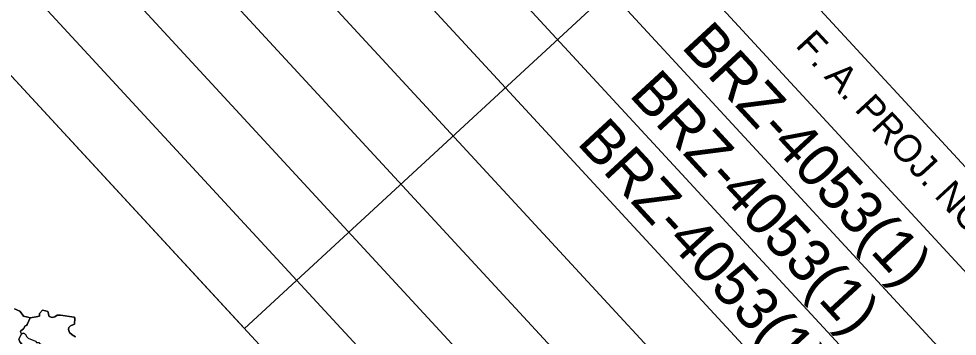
# Model space of a CAD drawing. Extents: x 1695041 to 1706254, y 786537 to 798223.
# Drawn here: x 1705302.9 to 1705798.2, y 794593.6 to 794761.2 of the extents above; entities that cross this region are included whole.
import ezdxf

# ---------------------------------------------------------------- set-up
doc = ezdxf.new("R2010")
doc.units = 0
for name, color, linetype in [('Old_Level_12', 7, 'Continuous'), ('Old_Level_20', 7, 'Continuous'), ('Sheet Data Field CELL', 7, 'Continuous'), ('Sheet Title CELL', 7, 'Continuous')]:
    doc.layers.add(name, color=color, linetype=linetype)

msp = doc.modelspace()

# ---------------------------------------------------------------- linework, layer by layer
at = {"layer": 'Old_Level_12'}
msp.add_lwpolyline([(1705795.09, 794193.47), (1705235.51, 794799.69), (1705053.77, 794631.93), (1705613.35, 794025.71)], close=True, dxfattribs=at)
at = {"layer": 'Old_Level_20'}
for points in [[(1705307.6, 794603.6), (1705305.47, 794604.25), (1705304.6, 794605.23), (1705303.49, 794606.78), (1705300.61, 794608.12)], [(1705300.61, 794608.12), (1705303.49, 794606.78), (1705304.6, 794605.23), (1705305.47, 794604.25), (1705307.6, 794603.6), (1705308.91, 794603.3)], [(1705308.91, 794603.3), (1705307.35, 794599.77), (1705306.94, 794599.3), (1705306.24, 794599), (1705305.34, 794597.53), (1705303.91, 794596.43), (1705303.86, 794595.84), (1705304.34, 794594.77), (1705302.96, 794592.03), (1705303.49, 794590.63), (1705304.49, 794589.47), (1705303.58, 794586.32), (1705302.57, 794585.14)], [(1705307.1, 794593.34), (1705306.56, 794594.37), (1705306.04, 794594.84), (1705305.33, 794595.19), (1705304.34, 794594.77), (1705303.86, 794595.84), (1705303.91, 794596.43), (1705305.34, 794597.53), (1705306.24, 794599), (1705306.94, 794599.3), (1705307.35, 794599.77), (1705308.91, 794603.3), (1705312.12, 794603.87), (1705313.75, 794604.17), (1705313.92, 794605.5), (1705315.35, 794607.26), (1705316.99, 794606.91), (1705318.16, 794606.7), (1705318.9, 794603.95), (1705320.47, 794603.55), (1705321.94, 794603.83), (1705323.18, 794604.69), (1705324.97, 794604.64)], [(1705332.89, 794593.24), (1705331.06, 794594.4), (1705329.74, 794595.62), (1705329.11, 794597.05), (1705329.24, 794598.17), (1705330.21, 794599.03), (1705332.29, 794600.02), (1705332.53, 794603.09), (1705332.09, 794603.72), (1705324.97, 794604.64), (1705323.18, 794604.69), (1705321.94, 794603.83), (1705320.47, 794603.55), (1705318.9, 794603.95), (1705318.16, 794606.7), (1705316.99, 794606.91), (1705315.35, 794607.26), (1705313.92, 794605.5), (1705313.75, 794604.17), (1705312.12, 794603.87), (1705308.91, 794603.3), (1705307.6, 794603.6)], [(1705324.97, 794604.64), (1705332.09, 794603.72), (1705332.53, 794603.09), (1705332.29, 794600.02), (1705330.21, 794599.03), (1705329.24, 794598.17), (1705329.11, 794597.05), (1705329.74, 794595.62), (1705331.06, 794594.4), (1705332.89, 794593.24)], [(1705302.57, 794585.14), (1705303.58, 794586.32), (1705304.49, 794589.47), (1705303.49, 794590.63), (1705302.96, 794592.03), (1705304.34, 794594.77), (1705305.33, 794595.19), (1705306.04, 794594.84), (1705306.56, 794594.37), (1705307.1, 794593.34), (1705307.88, 794592.49), (1705311.76, 794590.92), (1705312.2, 794590.29), (1705312.91, 794590.32), (1705313.56, 794590.31), (1705313.94, 794589.65), (1705315.17, 794589.2), (1705321.21, 794587.16), (1705325.86, 794585.65), (1705327.62, 794585.38)]]:
    msp.add_lwpolyline(points, dxfattribs=at)
at = {"layer": 'Sheet Title CELL'}
for points in [[(1706125.75, 794498.7), (1705566.15, 795104.89), (1705235.51, 794799.69), (1705421.98, 794597.63), (1705669.98, 794826.55), (1705559.79, 794945.92), (1705642.48, 795022.25), (1705973.14, 794663.98)], [(1706043.09, 794422.39), (1705483.51, 795028.61), (1705538.62, 795079.48), (1706098.2, 794473.26)], [(1705987.95, 794371.5), (1705428.37, 794977.71), (1705455.93, 795003.15), (1706015.51, 794396.93)], [(1705932.87, 794320.65), (1705373.29, 794926.87), (1705400.82, 794952.28), (1705960.42, 794346.09)], [(1705877.73, 794269.75), (1705318.18, 794875.94), (1705345.73, 794901.43), (1705905.31, 794295.22)], [(1705822.62, 794218.88), (1705263.07, 794825.13), (1705290.6, 794850.54), (1705850.17, 794244.32)], [(1705235.51, 794799.69), (1705795.09, 794193.47)]]:
    msp.add_lwpolyline(points, dxfattribs=at)

# ---------------------------------------------------------------- texts
at = {"layer": 'Sheet Data Field CELL'}
for p in [(1705652.08, 794746.2), (1705624.53, 794720.76), (1705597, 794695.35)]:
    msp.add_text('BRZ-4053(1)   ', height=22.5, rotation=312.7091, dxfattribs=at).set_placement(p)
at = {"layer": 'Sheet Title CELL'}
for s, height, p in [('STATE PROJECT REFERENCE NO.', 14.9994, (1705697.81, 794927.98)), ('F. A. PROJ. NO.', 14.4, (1705712.35, 794746.86))]:
    msp.add_text(s, height=height, rotation=312.7091, dxfattribs=at).set_placement(p)

doc.saveas('drawing.dxf')
